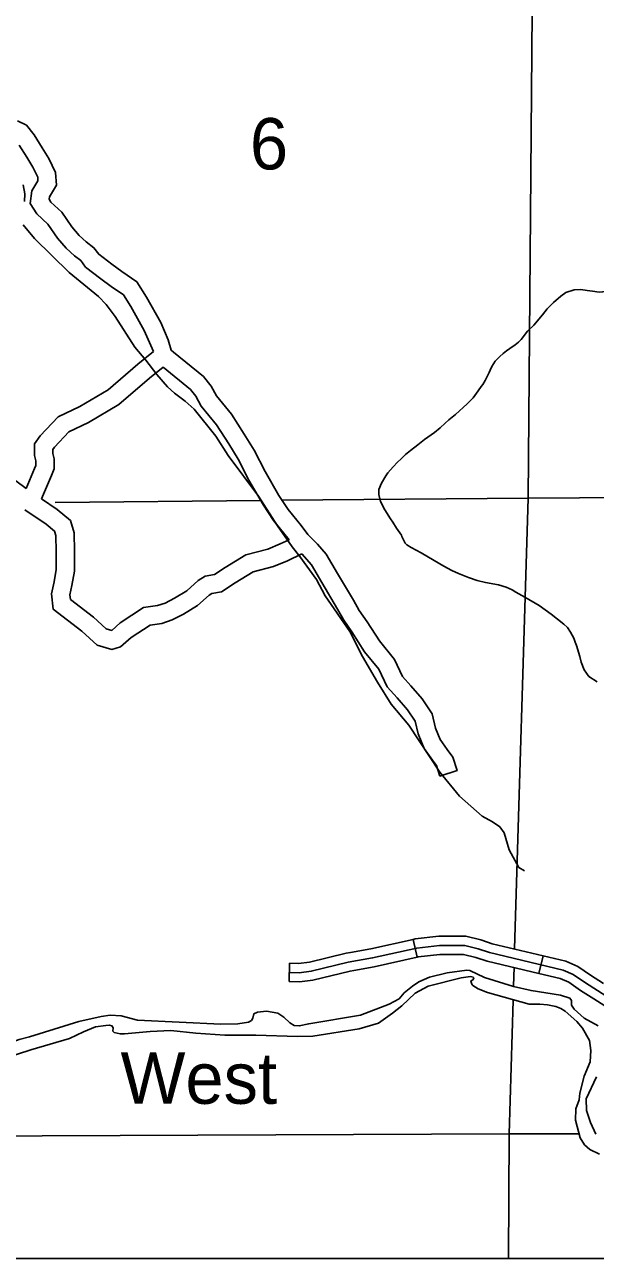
# Model space of a CAD drawing. Extents: x 1373862 to 1376999, y 1168398 to 1170455.
# Drawn here: x 1375575.6 to 1375669.4, y 1168563 to 1168765.8 of the extents above; entities that cross this region are included whole.
import ezdxf

# ---------------------------------------------------------------- set-up
doc = ezdxf.new("R2010")
doc.units = 0
for name, color, linetype in [('Level 35', 7, 'Continuous'), ('Level 45', 7, 'Continuous'), ('Level 46', 7, 'Continuous'), ('Level 5', 7, 'Continuous'), ('R_Draft', 7, 'Continuous')]:
    doc.layers.add(name, color=color, linetype=linetype)

msp = doc.modelspace()

# ---------------------------------------------------------------- linework, layer by layer
at = {"layer": 'Level 35'}
for points in [[(1375680.57, 1168722.85), (1375679.07, 1168722.37), (1375677.67, 1168722.07), (1375675.74, 1168721.82), (1375673.85, 1168722), (1375672.13, 1168722.09), (1375671.32, 1168722.05), (1375670.58, 1168721.91), (1375670.02, 1168721.84), (1375668.92, 1168722), (1375668.05, 1168722.14), (1375666.99, 1168722.31), (1375665.9, 1168722.25), (1375664.56, 1168721.83), (1375663.7, 1168721.22), (1375662.5, 1168720.18), (1375661.46, 1168719.1), (1375660.68, 1168718.11), (1375659.26, 1168716.41), (1375658.22, 1168715.42), (1375657.2, 1168714.06), (1375656.78, 1168713.66), (1375656.22, 1168713.18)], [(1375656.22, 1168713.18), (1375655.32, 1168712.59), (1375654.79, 1168712.21), (1375654.21, 1168711.79), (1375653.67, 1168711.29), (1375652.93, 1168710.52), (1375652.37, 1168709.64), (1375652.11, 1168709.02), (1375651.96, 1168708.64), (1375651.3, 1168707.34), (1375650.88, 1168706.68), (1375650.62, 1168706.33), (1375650.14, 1168705.63), (1375649.32, 1168704.49), (1375648.34, 1168703.51), (1375646.38, 1168701.76), (1375645.31, 1168700.87), (1375644.71, 1168700.33), (1375643.89, 1168699.57), (1375642.93, 1168698.79), (1375641.31, 1168697.62), (1375640.23, 1168696.78), (1375638.99, 1168695.83), (1375638.19, 1168695.15), (1375637.45, 1168694.45), (1375636.89, 1168693.9), (1375636.16, 1168693.16), (1375635.28, 1168692.14), (1375634.97, 1168691.66), (1375634.23, 1168690.45), (1375633.81, 1168689.41), (1375633.79, 1168688.57), (1375634.09, 1168687.43), (1375634.76, 1168686.09), (1375635.69, 1168684.56), (1375636.09, 1168684.02), (1375636.72, 1168683.06), (1375637.52, 1168681.9), (1375637.58, 1168681.66), (1375638.11, 1168680.6), (1375638.41, 1168680.3), (1375639.11, 1168679.86), (1375640.76, 1168678.99), (1375642.91, 1168677.73), (1375644.48, 1168676.82), (1375645.81, 1168676.1), (1375646.87, 1168675.6), (1375648.52, 1168674.95), (1375649.95, 1168674.47), (1375651.33, 1168674.14), (1375653.44, 1168673.72), (1375654.7, 1168673.35), (1375655.69, 1168672.89), (1375656.33, 1168672.53), (1375657.78, 1168671.73), (1375660.15, 1168670.36), (1375662.1, 1168668.91), (1375664.21, 1168667.27), (1375664.82, 1168666.71), (1375665.32, 1168665.93), (1375665.83, 1168664.99), (1375666.09, 1168664.3), (1375666.27, 1168663.76), (1375666.82, 1168661.94), (1375667.08, 1168661.02), (1375667.53, 1168659.76), (1375668.33, 1168658.66), (1375669.68, 1168657.78)], [(1375576.37, 1168599.43), (1375584.49, 1168601.91), (1375588.18, 1168602.77), (1375589.67, 1168602.99), (1375591.47, 1168602.88), (1375594.11, 1168602.15), (1375607.83, 1168601.48), (1375610.6, 1168601.56), (1375612.39, 1168601.83), (1375612.88, 1168602.12), (1375613.11, 1168602.48), (1375613.28, 1168603.2), (1375613.84, 1168603.45), (1375615.31, 1168603.62), (1375617.19, 1168603.33), (1375618.17, 1168602.67), (1375619.15, 1168601.7), (1375619.91, 1168601.3), (1375620.71, 1168601.21), (1375622.28, 1168601.55), (1375630.76, 1168602.95), (1375635.52, 1168604.77), (1375637.13, 1168605.66), (1375637.99, 1168606.63), (1375639.35, 1168607.77), (1375640.4, 1168608.45), (1375642.14, 1168609.22), (1375645.03, 1168609.92), (1375648.29, 1168610.38), (1375648.75, 1168610.33), (1375651.16, 1168609.17), (1375655.95, 1168607.67), (1375658.81, 1168607.03), (1375663.63, 1168606.25), (1375665.21, 1168605.76), (1375665.48, 1168605.4), (1375665.49, 1168604.63), (1375665.88, 1168603.95), (1375667.56, 1168602.46), (1375669.83, 1168601.22)], [(1375670.08, 1168580.12), (1375668.47, 1168580.87), (1375667.62, 1168581.66), (1375666.91, 1168582.82), (1375666.14, 1168585.71), (1375666.19, 1168587.55), (1375666.72, 1168589.04), (1375666.82, 1168590.16), (1375667.56, 1168592.93), (1375668.55, 1168595.28), (1375668.66, 1168597.16), (1375668.45, 1168598.82), (1375667.26, 1168600.86), (1375666.35, 1168601.96), (1375664.45, 1168603.61), (1375663.72, 1168604.06), (1375662.88, 1168604.42), (1375661.52, 1168604.68), (1375660.26, 1168604.8), (1375658.49, 1168604.79), (1375651.64, 1168606.72), (1375650.12, 1168607.29), (1375649.25, 1168607.84), (1375649.11, 1168608.05), (1375648.94, 1168608.57), (1375649.32, 1168608.82), (1375649.41, 1168609.1), (1375649.29, 1168609.22), (1375648.85, 1168609.31), (1375647.34, 1168609.14), (1375641.9, 1168607.77), (1375639.75, 1168606.58), (1375637.59, 1168604.53), (1375636.02, 1168603.28)], [(1375636.02, 1168603.28), (1375633.73, 1168601.66), (1375630.58, 1168600.73), (1375622.97, 1168599.53), (1375620.42, 1168599.46), (1375613.6, 1168599.71), (1375608.48, 1168599.71), (1375603.71, 1168599.99), (1375599.62, 1168600.44), (1375596.23, 1168600.28), (1375591.98, 1168599.89), (1375591.28, 1168599.92), (1375590.28, 1168600.13), (1375590.09, 1168600.34), (1375590.11, 1168600.88), (1375589.94, 1168601.22), (1375589.56, 1168601.33), (1375588.92, 1168601.3), (1375587.21, 1168601.08), (1375585.27, 1168600.26), (1375582.94, 1168599.13), (1375576.58, 1168597.29)], [(1375576.37, 1168599.43), (1375574.71, 1168598.97), (1375571.85, 1168597.95), (1375568.7, 1168597.02), (1375565.5, 1168595.87)], [(1375576.58, 1168597.29), (1375572.36, 1168595.88), (1375568.61, 1168594.98), (1375566.32, 1168594.69), (1375565.51, 1168594.46)], [(1375669.57, 1168592.86), (1375667.86, 1168589.24), (1375667.93, 1168587.32), (1375668.6, 1168585.31), (1375669.49, 1168583.41)]]:
    msp.add_lwpolyline(points, dxfattribs=at)
at = {"layer": 'Level 45'}
for p, q in [((1375640.08, 1168612.5), (1375639.43, 1168615.43)), ((1375660.11, 1168609.83), (1375660.8, 1168612.74)), ((1375619.04, 1168608.5), (1375619.09, 1168611.5))]:
    msp.add_line(p, q, dxfattribs=at)
for points in [[(1375575.32, 1168739.49), (1375575.61, 1168738.01), (1375575.59, 1168736.79)], [(1375575.33, 1168732.94), (1375577.22, 1168730.7), (1375582.89, 1168725.1), (1375587.75, 1168721.12), (1375588.97, 1168719.81), (1375590.47, 1168717.84), (1375593.72, 1168712.8), (1375595.49, 1168710.68), (1375597.3, 1168708.33), (1375599.07, 1168706.31), (1375600.21, 1168705.23), (1375601.99, 1168703.95), (1375603.43, 1168702.64), (1375607.01, 1168698.18), (1375609.06, 1168694.98), (1375614.01, 1168688.29), (1375617.15, 1168683.42), (1375619.54, 1168680.01), (1375620.84, 1168678.42), (1375623.54, 1168674.59), (1375624.97, 1168671.9), (1375629.01, 1168666.06), (1375631.1, 1168661.96), (1375633.56, 1168657.71), (1375635.83, 1168654.13), (1375638.74, 1168650.64), (1375643.82, 1168642.91), (1375647.04, 1168639), (1375650.78, 1168635.7), (1375652.49, 1168634.75), (1375653.66, 1168633.95), (1375654.39, 1168632.95), (1375655.21, 1168630.16), (1375656.82, 1168627.27), (1375657.73, 1168626.72)], [(1375619.06, 1168609.97), (1375620.7, 1168609.94), (1375622.69, 1168610.19), (1375628.77, 1168611.67), (1375632.76, 1168612.39), (1375640.04, 1168614), (1375643.75, 1168614.41), (1375647.91, 1168614.42), (1375650.13, 1168613.89), (1375652.01, 1168613.26), (1375664.07, 1168610.4), (1375665.74, 1168609.67), (1375667.74, 1168608.28), (1375672.47, 1168605.26)], [(1375629.15, 1168613.29), (1375632.46, 1168613.88), (1375639.43, 1168615.43)], [(1375639.43, 1168615.43), (1375639.79, 1168615.51), (1375643.66, 1168615.94), (1375648.09, 1168615.95), (1375650.55, 1168615.36), (1375650.71, 1168615.31)], [(1375650.71, 1168615.31), (1375652.43, 1168614.73), (1375660.8, 1168612.74)], [(1375619.09, 1168611.5), (1375620.62, 1168611.47), (1375622.42, 1168611.69), (1375628.45, 1168613.17), (1375629.15, 1168613.29)], [(1375629.68, 1168610.34), (1375633.05, 1168610.94), (1375640.08, 1168612.5)], [(1375640.08, 1168612.5), (1375640.28, 1168612.54), (1375643.83, 1168612.94), (1375647.74, 1168612.95), (1375649.72, 1168612.48), (1375649.75, 1168612.47)], [(1375649.75, 1168612.47), (1375651.6, 1168611.84), (1375660.11, 1168609.83)], [(1375660.8, 1168612.74), (1375664.56, 1168611.85), (1375666.49, 1168611), (1375668.58, 1168609.55), (1375670.73, 1168608.18)], [(1375619.04, 1168608.5), (1375620.78, 1168608.47), (1375622.96, 1168608.74), (1375629.07, 1168610.23), (1375629.68, 1168610.34)], [(1375660.11, 1168609.83), (1375663.6, 1168609), (1375665.02, 1168608.38), (1375666.92, 1168607.05), (1375669.12, 1168605.65)], [(1375669.12, 1168605.65), (1375671.53, 1168604.12), (1375672.98, 1168602.61), (1375674.57, 1168601.31), (1375676.28, 1168600.06), (1375677.45, 1168599.28)]]:
    msp.add_lwpolyline(points, dxfattribs=at)
at = {"layer": 'Level 46'}
for points in [[(1375574.39, 1168750.01), (1375575.88, 1168749.34), (1375577.13, 1168747.74), (1375578.48, 1168745.61), (1375579.54, 1168743.83), (1375580.68, 1168741.55), (1375580.82, 1168739.44), (1375579.66, 1168737.51), (1375579.61, 1168737.13), (1375579.91, 1168736.68), (1375581.69, 1168734.99), (1375583.33, 1168732.6), (1375584.56, 1168731.2), (1375585.7, 1168730.14), (1375586.96, 1168729.17), (1375587.77, 1168728.1), (1375589.91, 1168726.45), (1375591.57, 1168725.23), (1375594.03, 1168723.55), (1375595.64, 1168721.02), (1375597.95, 1168716.86), (1375599.17, 1168714.04), (1375599.69, 1168712.32), (1375600.06, 1168711.99), (1375604.98, 1168707.98), (1375606.23, 1168706.42), (1375607.12, 1168704.82), (1375609.56, 1168701.81), (1375611.66, 1168698.51), (1375613.31, 1168695.87), (1375615.1, 1168692.37), (1375617.37, 1168688.43), (1375618.92, 1168686.11), (1375621.03, 1168683.47), (1375622.14, 1168682), (1375623.7, 1168680.44), (1375625.16, 1168678.78), (1375627.02, 1168675.62), (1375629.61, 1168671.24), (1375630.56, 1168669.51), (1375631.87, 1168667.66), (1375633.89, 1168664.5), (1375636.36, 1168661.48), (1375637.68, 1168658.65), (1375639.06, 1168657.11), (1375640.91, 1168654.98), (1375642.54, 1168652.54), (1375643.11, 1168650.17), (1375643.89, 1168648.29), (1375645.03, 1168646.66), (1375645.97, 1168645.4), (1375646.67, 1168643.2), (1375643.81, 1168642.29)], [(1375574.68, 1168746.01), (1375575.92, 1168744.04), (1375576.91, 1168742.39), (1375577.73, 1168740.74), (1375577.76, 1168740.18), (1375576.78, 1168738.53), (1375576.48, 1168736.42), (1375577.6, 1168734.73), (1375579.39, 1168733.03), (1375580.96, 1168730.75), (1375582.4, 1168729.11), (1375583.76, 1168727.85), (1375584.81, 1168727.04), (1375585.61, 1168725.97), (1375588.1, 1168724.05), (1375589.83, 1168722.78), (1375591.83, 1168721.42), (1375593.06, 1168719.49), (1375595.25, 1168715.53), (1375596.75, 1168712.08)], [(1375596.75, 1168712.08), (1375594.2, 1168710.04), (1375589.29, 1168705.82), (1375584.65, 1168703.07), (1375581.07, 1168701.37), (1375578.12, 1168698.23), (1375577.22, 1168696.91), (1375577.22, 1168694.99), (1375577.42, 1168694.1), (1375577.42, 1168693.34), (1375577.23, 1168692.84), (1375575.81, 1168689.57)], [(1375598.35, 1168709.52), (1375596.11, 1168707.73), (1375591.04, 1168703.38), (1375586.06, 1168700.42), (1375582.87, 1168698.91), (1375580.47, 1168696.35), (1375580.22, 1168695.99), (1375580.22, 1168695.32), (1375580.42, 1168694.43), (1375580.42, 1168692.8), (1375580.01, 1168691.71), (1375578.33, 1168687.86)], [(1375598.35, 1168709.52), (1375602.84, 1168705.86), (1375603.73, 1168704.74), (1375604.62, 1168703.13), (1375607.13, 1168700.05), (1375609.13, 1168696.92), (1375610.69, 1168694.39), (1375612.46, 1168690.93), (1375614.82, 1168686.84), (1375616.49, 1168684.34), (1375619.05, 1168681.14)], [(1375575.81, 1168689.57), (1375572.21, 1168692.27)], [(1375578.33, 1168687.86), (1375580.91, 1168686.14), (1375583.1, 1168684.31), (1375583.71, 1168682.31), (1375583.76, 1168679.24), (1375583.79, 1168675.97), (1375583.36, 1168673.61), (1375583.02, 1168672.1), (1375583.11, 1168671.34), (1375586.92, 1168668.41), (1375589, 1168666.52), (1375589.91, 1168666.25), (1375591.3, 1168667.47), (1375595.14, 1168669.99), (1375597.42, 1168670.32), (1375598.66, 1168670.73), (1375600.2, 1168671.55), (1375602.23, 1168672.75), (1375604.1, 1168674.42), (1375605.24, 1168675.14), (1375606.81, 1168675.43), (1375608.56, 1168676.57), (1375611.94, 1168678.68), (1375615.54, 1168679.61), (1375617.59, 1168680.45), (1375619.05, 1168681.14)], [(1375575.61, 1168686.07), (1375579.11, 1168683.73), (1375580.49, 1168682.58), (1375580.72, 1168681.84), (1375580.76, 1168679.2), (1375580.79, 1168676.23), (1375580.42, 1168674.21), (1375579.98, 1168672.26), (1375580.28, 1168669.73), (1375585, 1168666.11), (1375587.49, 1168663.84), (1375589.92, 1168663.12), (1375591.36, 1168663.53), (1375593.12, 1168665.07), (1375596.22, 1168667.12), (1375598.11, 1168667.39), (1375599.84, 1168667.96), (1375601.67, 1168668.93), (1375604.01, 1168670.32), (1375605.91, 1168672.02), (1375606.35, 1168672.29), (1375607.95, 1168672.59), (1375610.17, 1168674.04), (1375613.14, 1168675.89), (1375616.48, 1168676.76), (1375618.8, 1168677.7), (1375621.13, 1168678.81)], [(1375621.13, 1168678.81), (1375622.72, 1168677.01), (1375624.43, 1168674.1), (1375627.01, 1168669.75), (1375628.02, 1168667.91), (1375629.38, 1168665.99), (1375631.46, 1168662.73), (1375633.8, 1168659.87), (1375635.15, 1168656.98), (1375636.81, 1168655.13), (1375638.52, 1168653.16), (1375639.75, 1168651.32), (1375640.25, 1168649.23), (1375641.25, 1168646.83), (1375642.6, 1168644.9), (1375643.27, 1168644.01), (1375643.81, 1168642.29)]]:
    msp.add_lwpolyline(points, dxfattribs=at)
at = {"layer": 'Level 5'}
for points in [[(1375658.32, 1168688.01), (1375659.21, 1168794.75)], [(1375580.63, 1168687.3), (1375614.38, 1168687.61)], [(1375617.83, 1168687.64), (1375658.32, 1168688.01), (1375708.96, 1168688.34)], [(1375656.12, 1168613.89), (1375658.32, 1168688.01)], [(1375655.94, 1168607.74), (1375656.03, 1168610.86)], [(1375655.09, 1168562.99), (1375655.22, 1168583.45), (1375655.87, 1168605.41)], [(1375565.63, 1168583.09), (1375655.22, 1168583.45), (1375666.69, 1168583.46)]]:
    msp.add_lwpolyline(points, dxfattribs=at)
at = {"layer": 'R_Draft'}
msp.add_lwpolyline([(1374675.34, 1169579.43), (1376182.76, 1169579.43), (1376182.76, 1168562.99), (1374675.34, 1168562.99)], close=True, dxfattribs=at)

# ---------------------------------------------------------------- texts
at = {"layer": 'Level 35'}
msp.add_text('West', height=8.44, dxfattribs=at).set_placement((1375591.36, 1168588.4))
at = {"layer": 'Level 5'}
msp.add_text('6', height=8.44, dxfattribs=at).set_placement((1375612.61, 1168742.04))

doc.saveas('drawing.dxf')
